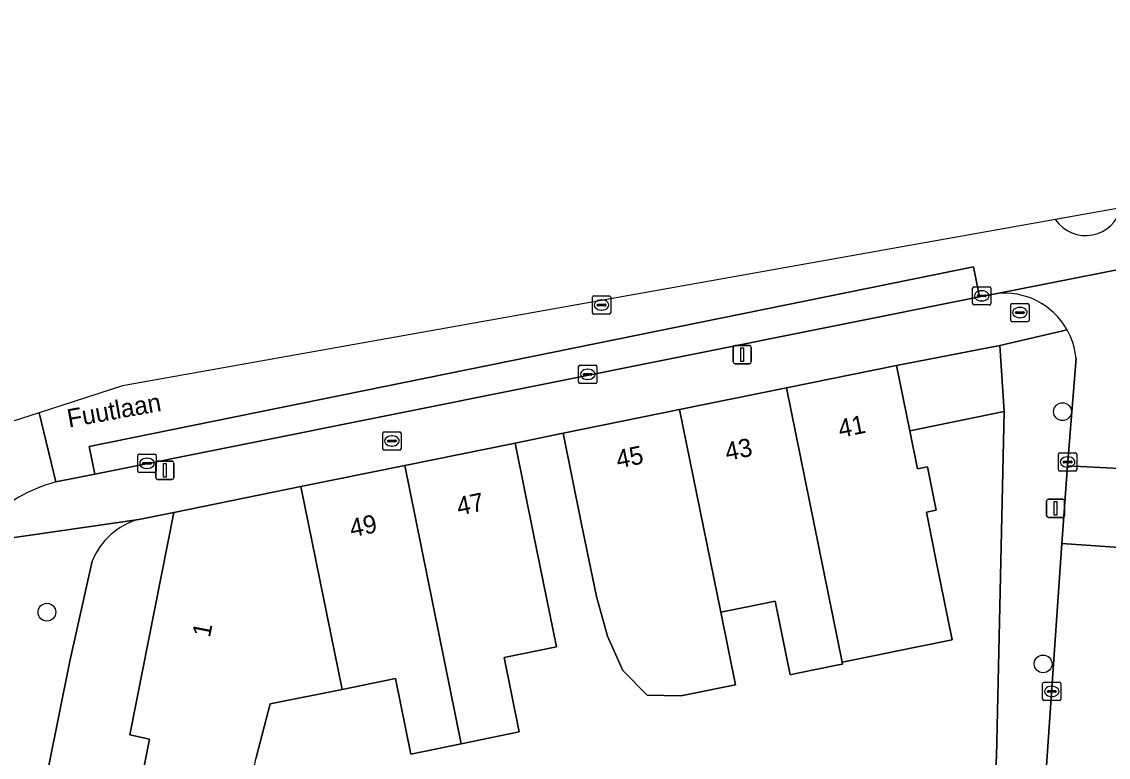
# Model space of a CAD drawing. Extents: x 161772 to 163126, y 383092 to 383917.
# Drawn here: x 162268.2 to 162327.9, y 383778.3 to 383818.6 of the extents above; entities that cross this region are included whole.
import ezdxf

# ---------------------------------------------------------------- set-up
doc = ezdxf.new("R2010")
doc.units = 0
for name, color, linetype in [('IMGEO_Boom', 7, 'Continuous'), ('IMGEO_Brandkraan', 7, 'Continuous'), ('IMGEO_Erf', 7, 'Continuous'), ('IMGEO_Kolk', 7, 'Continuous'), ('IMGEO_Lichtmast', 7, 'Continuous'), ('IMGEO_Openbare_ruimte_label', 7, 'Continuous'), ('IMGEO_Pand', 7, 'Continuous'), ('IMGEO_Pand_nummerreeks', 7, 'Continuous'), ('IMGEO_Parkeervlak_open', 7, 'Continuous'), ('IMGEO_Rijbaan_lokaal_open', 7, 'Continuous'), ('IMGEO_Rioolput', 7, 'Continuous'), ('IMGEO_Voetpad_open', 7, 'Continuous')]:
    doc.layers.add(name, color=color, linetype=linetype)

msp = doc.modelspace()

# ---------------------------------------------------------------- linework, layer by layer
at = {"layer": 'IMGEO_Boom'}
for centre in [(162325.344, 383797.219), (162269.629, 383786.219), (162324.279, 383783.385)]:
    msp.add_circle(centre, 0.489, dxfattribs=at)
at = {"layer": 'IMGEO_Brandkraan'}
for p, q in [((162322.507, 383802.226), (162322.507, 383803.078)), ((162322.582, 383803.152), (162323.434, 383803.152)), ((162323.508, 383803.078), (162323.508, 383802.226)), ((162322.766, 383802.646), (162322.766, 383802.658)), ((162323.204, 383802.609), (162322.806, 383802.609)), ((162322.809, 383802.695), (162323.207, 383802.695)), ((162322.995, 383802.932), (162323.02, 383802.932)), ((162323.25, 383802.658), (162323.25, 383802.646)), ((162323.434, 383802.152), (162322.582, 383802.152)), ((162323.018, 383802.372), (162322.993, 383802.372)), ((162288.055, 383795.184), (162288.055, 383796.036)), ((162288.13, 383796.11), (162288.982, 383796.11)), ((162288.543, 383795.89), (162288.568, 383795.89)), ((162289.056, 383796.036), (162289.056, 383795.184)), ((162288.314, 383795.604), (162288.314, 383795.616)), ((162288.752, 383795.567), (162288.354, 383795.567)), ((162288.357, 383795.653), (162288.755, 383795.653)), ((162288.566, 383795.33), (162288.541, 383795.33)), ((162288.798, 383795.616), (162288.798, 383795.604)), ((162288.982, 383795.11), (162288.13, 383795.11))]:
    msp.add_line(p, q, dxfattribs=at)
for points in [[(162322.507, 383802.226), (162322.507, 383803.078)], [(162322.582, 383803.152), (162323.434, 383803.152)], [(162323.508, 383803.078), (162323.508, 383802.226)], [(162323.434, 383802.152), (162322.582, 383802.152)], [(162288.055, 383795.184), (162288.055, 383796.036)], [(162288.13, 383796.11), (162288.982, 383796.11)], [(162289.056, 383796.036), (162289.056, 383795.184)], [(162288.982, 383795.11), (162288.13, 383795.11)]]:
    msp.add_lwpolyline(points, dxfattribs=at)
for centre, radius, start, end in [((162322.584, 383803.076), 0.0765, 91.55205, 178.44795), ((162322.584, 383803.076), 0.0765, 91.55205, 178.44795), ((162323.432, 383803.076), 0.0765, 1.55205, 88.44795), ((162323.432, 383803.076), 0.0765, 1.55205, 88.44795), ((162322.806, 383802.655), 0.0403, 85.87752, 175.75265), ((162322.803, 383802.645), 0.0366, 178.93798, 274.71019), ((162323.207, 383802.652), 0.043, 264.86636, 352.45326), ((162323.211, 383802.657), 0.0386, 1.73085, 96.63898), ((162322.584, 383802.228), 0.0765, 181.55205, 268.44795), ((162322.584, 383802.228), 0.0765, 181.55205, 268.44795), ((162323.432, 383802.228), 0.0765, 271.55205, 358.44795), ((162323.432, 383802.228), 0.0765, 271.55205, 358.44795), ((162288.132, 383796.034), 0.0765, 91.55205, 178.44795), ((162288.132, 383796.034), 0.0765, 91.55205, 178.44795), ((162288.98, 383796.034), 0.0765, 1.55205, 88.44795), ((162288.98, 383796.034), 0.0765, 1.55205, 88.44795), ((162288.354, 383795.613), 0.0403, 85.87752, 175.75265), ((162288.351, 383795.603), 0.0366, 178.93798, 274.71019), ((162288.755, 383795.61), 0.043, 264.86636, 352.45326), ((162288.759, 383795.615), 0.0386, 1.73085, 96.63898), ((162288.132, 383795.186), 0.0765, 181.55205, 268.44795), ((162288.132, 383795.186), 0.0765, 181.55205, 268.44795), ((162288.98, 383795.186), 0.0765, 271.55205, 358.44795), ((162288.98, 383795.186), 0.0765, 271.55205, 358.44795)]:
    msp.add_arc(centre, radius, start, end, dxfattribs=at)
for centre, major_axis, ratio, start_param, end_param in [((162322.994, 383802.652), (-0.387, 0.002), 0.722429, 4.712389, 7.853982), ((162323.019, 383802.652), (-0.39, 0.002), 0.717154, 1.570796, 4.712389), ((162288.542, 383795.61), (-0.387, 0.002), 0.722429, 4.712389, 7.853982), ((162288.567, 383795.61), (-0.39, 0.002), 0.717154, 1.570796, 4.712389)]:
    msp.add_ellipse(centre, major_axis=major_axis, ratio=ratio, start_param=start_param, end_param=end_param, dxfattribs=at)
at = {"layer": 'IMGEO_Erf'}
for points in [[(162319.862, 383750), (162321.727, 383778.3), (162322.139, 383797.223), (162316.967, 383796.173), (162317.392, 383794.081), (162317.931, 383794.19), (162318.413, 383791.815), (162317.874, 383791.705), (162318.457, 383788.836), (162319.295, 383784.711), (162316.12, 383784.066), (162315.248, 383783.889), (162313.255, 383783.484), (162313.276, 383783.377), (162313.058, 383783.333), (162310.891, 383782.893), (162310.398, 383782.793), (162309.58, 383786.821), (162308.063, 383786.513), (162306.602, 383786.217), (162307.41, 383782.245), (162304.407, 383781.634), (162302.554, 383781.68), (162301.226, 383783.033), (162300.375, 383784.913), (162299.786, 383787.082), (162298.945, 383791.139), (162297.95, 383796.038), (162295.313, 383795.494), (162296.309, 383790.595), (162297.584, 383784.328), (162294.712, 383783.744), (162295.544, 383779.654), (162292.357, 383779.006), (162289.591, 383778.444), (162288.749, 383782.585), (162285.824, 383781.991), (162281.88, 383781.189), (162281.098, 383778.183)], [(162272.117, 383789.029), (162270.877, 383783.542), (162269.728, 383777.815), (162274.763, 383776.75), (162275.261, 383779.268), (162274.173, 383779.503), (162276.595, 383791.688)], [(162276.595, 383791.688), (162274.674, 383791.312)]]:
    msp.add_lwpolyline(points, dxfattribs=at)
msp.add_arc((162275.675, 383787.617), 3.828, 105.16115, 158.35856, dxfattribs=at)
at = {"layer": 'IMGEO_Kolk'}
for p, q in [((162320.412, 383803.142), (162320.412, 383803.994)), ((162320.487, 383804.068), (162321.339, 383804.068)), ((162320.714, 383803.611), (162321.112, 383803.611)), ((162320.9, 383803.848), (162320.925, 383803.848)), ((162321.413, 383803.994), (162321.413, 383803.142)), ((162321.339, 383803.068), (162320.487, 383803.068)), ((162320.671, 383803.562), (162320.671, 383803.574)), ((162321.109, 383803.525), (162320.711, 383803.525)), ((162320.923, 383803.288), (162320.898, 383803.288)), ((162321.155, 383803.574), (162321.155, 383803.562)), ((162298.798, 383798.839), (162298.798, 383799.691)), ((162298.873, 383799.765), (162299.725, 383799.765)), ((162299.286, 383799.545), (162299.311, 383799.545)), ((162299.799, 383799.691), (162299.799, 383798.839)), ((162299.057, 383799.259), (162299.057, 383799.271)), ((162299.495, 383799.222), (162299.097, 383799.222)), ((162299.1, 383799.308), (162299.498, 383799.308)), ((162299.309, 383798.985), (162299.284, 383798.985)), ((162299.541, 383799.271), (162299.541, 383799.259)), ((162299.725, 383798.765), (162298.873, 383798.765)), ((162274.619, 383793.959), (162274.619, 383794.811)), ((162274.694, 383794.885), (162275.546, 383794.885)), ((162275.107, 383794.665), (162275.132, 383794.665)), ((162275.62, 383794.811), (162275.62, 383793.959)), ((162325.123, 383794.032), (162325.123, 383794.884)), ((162325.198, 383794.958), (162326.05, 383794.958)), ((162325.611, 383794.738), (162325.636, 383794.738)), ((162326.124, 383794.884), (162326.124, 383794.032)), ((162274.878, 383794.379), (162274.878, 383794.391)), ((162275.316, 383794.342), (162274.918, 383794.342)), ((162274.921, 383794.428), (162275.319, 383794.428)), ((162275.13, 383794.105), (162275.105, 383794.105)), ((162275.362, 383794.391), (162275.362, 383794.379)), ((162325.382, 383794.452), (162325.382, 383794.464)), ((162325.82, 383794.415), (162325.422, 383794.415)), ((162325.425, 383794.501), (162325.823, 383794.501)), ((162325.634, 383794.178), (162325.609, 383794.178)), ((162325.866, 383794.464), (162325.866, 383794.452)), ((162275.546, 383793.885), (162274.694, 383793.885)), ((162326.05, 383793.958), (162325.198, 383793.958)), ((162324.253, 383781.452), (162324.253, 383782.304)), ((162324.328, 383782.378), (162325.18, 383782.378)), ((162324.741, 383782.158), (162324.766, 383782.158)), ((162325.254, 383782.304), (162325.254, 383781.452)), ((162324.512, 383781.872), (162324.512, 383781.884)), ((162324.95, 383781.835), (162324.552, 383781.835)), ((162324.555, 383781.921), (162324.953, 383781.921)), ((162324.764, 383781.598), (162324.739, 383781.598)), ((162324.996, 383781.884), (162324.996, 383781.872)), ((162325.18, 383781.378), (162324.328, 383781.378))]:
    msp.add_line(p, q, dxfattribs=at)
for points in [[(162320.412, 383803.142), (162320.412, 383803.994)], [(162320.487, 383804.068), (162321.339, 383804.068)], [(162321.413, 383803.994), (162321.413, 383803.142)], [(162321.339, 383803.068), (162320.487, 383803.068)], [(162298.798, 383798.839), (162298.798, 383799.691)], [(162298.873, 383799.765), (162299.725, 383799.765)], [(162299.799, 383799.691), (162299.799, 383798.839)], [(162299.725, 383798.765), (162298.873, 383798.765)], [(162274.619, 383793.959), (162274.619, 383794.811)], [(162274.694, 383794.885), (162275.546, 383794.885)], [(162275.62, 383794.811), (162275.62, 383793.959)], [(162325.123, 383794.032), (162325.123, 383794.884)], [(162325.198, 383794.958), (162326.05, 383794.958)], [(162326.124, 383794.884), (162326.124, 383794.032)], [(162275.546, 383793.885), (162274.694, 383793.885)], [(162326.05, 383793.958), (162325.198, 383793.958)], [(162324.253, 383781.452), (162324.253, 383782.304)], [(162324.328, 383782.378), (162325.18, 383782.378)], [(162325.254, 383782.304), (162325.254, 383781.452)], [(162325.18, 383781.378), (162324.328, 383781.378)]]:
    msp.add_lwpolyline(points, dxfattribs=at)
for centre, radius, start, end in [((162320.489, 383803.992), 0.0765, 91.55205, 178.44795), ((162320.489, 383803.992), 0.0765, 91.55205, 178.44795), ((162320.711, 383803.571), 0.0403, 85.87752, 175.75265), ((162321.116, 383803.573), 0.0386, 1.73085, 96.63898), ((162321.337, 383803.992), 0.0765, 1.55205, 88.44795), ((162321.337, 383803.992), 0.0765, 1.55205, 88.44795), ((162320.489, 383803.144), 0.0765, 181.55205, 268.44795), ((162320.489, 383803.144), 0.0765, 181.55205, 268.44795), ((162320.708, 383803.561), 0.0366, 178.93798, 274.71019), ((162321.112, 383803.568), 0.043, 264.86636, 352.45326), ((162321.337, 383803.144), 0.0765, 271.55205, 358.44795), ((162321.337, 383803.144), 0.0765, 271.55205, 358.44795), ((162298.875, 383799.689), 0.0765, 91.55205, 178.44795), ((162298.875, 383799.689), 0.0765, 91.55205, 178.44795), ((162299.723, 383799.689), 0.0765, 1.55205, 88.44795), ((162299.723, 383799.689), 0.0765, 1.55205, 88.44795), ((162298.875, 383798.841), 0.0765, 181.55205, 268.44795), ((162298.875, 383798.841), 0.0765, 181.55205, 268.44795), ((162299.097, 383799.268), 0.0403, 85.87752, 175.75265), ((162299.094, 383799.258), 0.0366, 178.93798, 274.71019), ((162299.498, 383799.265), 0.043, 264.86636, 352.45326), ((162299.502, 383799.27), 0.0386, 1.73085, 96.63898), ((162299.723, 383798.841), 0.0765, 271.55205, 358.44795), ((162299.723, 383798.841), 0.0765, 271.55205, 358.44795), ((162274.696, 383794.809), 0.0765, 91.55205, 178.44795), ((162274.696, 383794.809), 0.0765, 91.55205, 178.44795), ((162275.544, 383794.809), 0.0765, 1.55205, 88.44795), ((162275.544, 383794.809), 0.0765, 1.55205, 88.44795), ((162325.2, 383794.882), 0.0765, 91.55205, 178.44795), ((162325.2, 383794.882), 0.0765, 91.55205, 178.44795), ((162326.048, 383794.882), 0.0765, 1.55205, 88.44795), ((162326.048, 383794.882), 0.0765, 1.55205, 88.44795), ((162274.918, 383794.388), 0.0403, 85.87752, 175.75265), ((162274.915, 383794.378), 0.0366, 178.93798, 274.71019), ((162275.319, 383794.385), 0.043, 264.86636, 352.45326), ((162275.323, 383794.39), 0.0386, 1.73085, 96.63898), ((162325.422, 383794.461), 0.0403, 85.87752, 175.75265), ((162325.419, 383794.451), 0.0366, 178.93798, 274.71019), ((162325.823, 383794.458), 0.043, 264.86636, 352.45326), ((162325.827, 383794.463), 0.0386, 1.73085, 96.63898), ((162274.696, 383793.961), 0.0765, 181.55205, 268.44795), ((162274.696, 383793.961), 0.0765, 181.55205, 268.44795), ((162275.544, 383793.961), 0.0765, 271.55205, 358.44795), ((162275.544, 383793.961), 0.0765, 271.55205, 358.44795), ((162325.2, 383794.034), 0.0765, 181.55205, 268.44795), ((162325.2, 383794.034), 0.0765, 181.55205, 268.44795), ((162326.048, 383794.034), 0.0765, 271.55205, 358.44795), ((162326.048, 383794.034), 0.0765, 271.55205, 358.44795), ((162324.33, 383782.302), 0.0765, 91.55205, 178.44795), ((162324.33, 383782.302), 0.0765, 91.55205, 178.44795), ((162325.178, 383782.302), 0.0765, 1.55205, 88.44795), ((162325.178, 383782.302), 0.0765, 1.55205, 88.44795), ((162324.552, 383781.881), 0.0403, 85.87752, 175.75265), ((162324.549, 383781.871), 0.0366, 178.93798, 274.71019), ((162324.953, 383781.878), 0.043, 264.86636, 352.45326), ((162324.957, 383781.883), 0.0386, 1.73085, 96.63898), ((162324.33, 383781.454), 0.0765, 181.55205, 268.44795), ((162324.33, 383781.454), 0.0765, 181.55205, 268.44795), ((162325.178, 383781.454), 0.0765, 271.55205, 358.44795), ((162325.178, 383781.454), 0.0765, 271.55205, 358.44795)]:
    msp.add_arc(centre, radius, start, end, dxfattribs=at)
for centre, major_axis, ratio, start_param, end_param in [((162320.899, 383803.568), (-0.387, 0.002), 0.722429, 4.712389, 7.853982), ((162320.924, 383803.568), (-0.39, 0.002), 0.717154, 1.570796, 4.712389), ((162299.285, 383799.265), (-0.387, 0.002), 0.722429, 4.712389, 7.853982), ((162299.31, 383799.265), (-0.39, 0.002), 0.717154, 1.570796, 4.712389), ((162275.106, 383794.385), (-0.387, 0.002), 0.722429, 4.712389, 7.853982), ((162275.131, 383794.385), (-0.39, 0.002), 0.717154, 1.570796, 4.712389), ((162325.61, 383794.458), (-0.387, 0.002), 0.722429, 4.712389, 7.853982), ((162325.635, 383794.458), (-0.39, 0.002), 0.717154, 1.570796, 4.712389), ((162324.74, 383781.878), (-0.387, 0.002), 0.722429, 4.712389, 7.853982), ((162324.765, 383781.878), (-0.39, 0.002), 0.717154, 1.570796, 4.712389)]:
    msp.add_ellipse(centre, major_axis=major_axis, ratio=ratio, start_param=start_param, end_param=end_param, dxfattribs=at)
at = {"layer": 'IMGEO_Lichtmast'}
for p, q in [((162307.281, 383799.949), (162307.281, 383800.749)), ((162307.281, 383800.749), (162307.281, 383799.949)), ((162307.381, 383800.849), (162308.171, 383800.849)), ((162308.171, 383800.849), (162307.381, 383800.849)), ((162308.271, 383800.749), (162308.271, 383799.949)), ((162308.271, 383799.949), (162308.271, 383800.749)), ((162308.171, 383799.849), (162307.381, 383799.849)), ((162307.381, 383799.849), (162308.171, 383799.849)), ((162275.603, 383793.596), (162275.603, 383794.396)), ((162275.603, 383794.396), (162275.603, 383793.596)), ((162275.703, 383794.496), (162276.493, 383794.496)), ((162276.493, 383794.496), (162275.703, 383794.496)), ((162276.593, 383794.396), (162276.593, 383793.596)), ((162276.593, 383793.596), (162276.593, 383794.396)), ((162276.493, 383793.496), (162275.703, 383793.496)), ((162275.703, 383793.496), (162276.493, 383793.496)), ((162324.468, 383791.515), (162324.468, 383792.315)), ((162324.468, 383792.315), (162324.468, 383791.515)), ((162324.568, 383792.415), (162325.358, 383792.415)), ((162325.358, 383792.415), (162324.568, 383792.415)), ((162325.458, 383792.315), (162325.458, 383791.515)), ((162325.458, 383791.515), (162325.458, 383792.315)), ((162325.358, 383791.415), (162324.568, 383791.415)), ((162324.568, 383791.415), (162325.358, 383791.415))]:
    msp.add_line(p, q, dxfattribs=at)
for points in [[(162307.701, 383800.724), (162307.851, 383800.724), (162307.851, 383799.974), (162307.701, 383799.974), (162307.701, 383800.724)], [(162276.023, 383794.371), (162276.173, 383794.371), (162276.173, 383793.621), (162276.023, 383793.621), (162276.023, 383794.371)], [(162324.888, 383792.29), (162325.038, 383792.29), (162325.038, 383791.54), (162324.888, 383791.54), (162324.888, 383792.29)]]:
    msp.add_lwpolyline(points, dxfattribs=at)
for centre, start, end in [((162307.381, 383800.749), 90, 180), ((162307.381, 383800.749), 90, 180), ((162308.171, 383800.749), 0, 90), ((162308.171, 383800.749), 360, 90), ((162307.381, 383799.949), 180, 270), ((162307.381, 383799.949), 180, 270), ((162308.171, 383799.949), 270, 0), ((162308.171, 383799.949), 270, 0), ((162275.703, 383794.396), 90, 180), ((162275.703, 383794.396), 90, 180), ((162276.493, 383794.396), 0, 90), ((162276.493, 383794.396), 360, 90), ((162275.703, 383793.596), 180, 270), ((162275.703, 383793.596), 180, 270), ((162276.493, 383793.596), 270, 0), ((162276.493, 383793.596), 270, 0), ((162324.568, 383792.315), 90, 180), ((162324.568, 383792.315), 90, 180), ((162325.358, 383792.315), 0, 90), ((162325.358, 383792.315), 360, 90), ((162324.568, 383791.515), 180, 270), ((162324.568, 383791.515), 180, 270), ((162325.358, 383791.515), 270, 0), ((162325.358, 383791.515), 270, 0)]:
    msp.add_arc(centre, 0.1, start, end, dxfattribs=at)
at = {"layer": 'IMGEO_Pand'}
for points in [[(162321.904, 383800.852), (162316.24, 383799.753), (162316.967, 383796.173), (162322.139, 383797.223)], [(162318.413, 383791.815), (162317.931, 383794.19), (162317.392, 383794.081), (162316.967, 383796.173), (162316.24, 383799.753), (162310.196, 383798.525), (162313.255, 383783.484), (162315.248, 383783.889), (162316.12, 383784.066), (162319.295, 383784.711), (162318.457, 383788.836), (162317.874, 383791.705)], [(162310.196, 383798.525), (162304.341, 383797.336), (162306.602, 383786.217), (162308.063, 383786.513), (162309.58, 383786.821), (162310.398, 383782.793), (162310.891, 383782.893), (162313.058, 383783.333), (162313.276, 383783.377), (162313.255, 383783.484)], [(162304.341, 383797.336), (162297.95, 383796.038), (162298.945, 383791.139), (162299.786, 383787.082), (162300.375, 383784.913), (162301.226, 383783.033), (162302.554, 383781.68), (162304.407, 383781.634), (162307.41, 383782.245), (162306.602, 383786.217)], [(162289.259, 383794.263), (162292.357, 383779.006), (162295.544, 383779.654), (162294.712, 383783.744), (162297.584, 383784.328), (162296.309, 383790.595), (162295.313, 383795.494)], [(162283.567, 383793.106), (162285.824, 383781.991), (162288.749, 383782.585), (162289.591, 383778.444), (162292.357, 383779.006), (162289.259, 383794.263)], [(162283.567, 383793.106), (162276.595, 383791.688), (162274.173, 383779.503), (162275.261, 383779.268), (162274.763, 383776.75), (162276.722, 383776.385), (162280.593, 383775.63), (162281.098, 383778.183), (162281.88, 383781.189), (162285.824, 383781.991)]]:
    msp.add_lwpolyline(points, close=True, dxfattribs=at)
at = {"layer": 'IMGEO_Parkeervlak_open'}
msp.add_lwpolyline([(162320.785, 383803.509), (162320.467, 383805.155), (162271.954, 383795.306), (162272.251, 383793.788)], close=True, dxfattribs=at)
at = {"layer": 'IMGEO_Rijbaan_lokaal_open'}
for points in [[(162324.958, 383807.747), (162273.78, 383798.628), (162269.209, 383797.162), (162270.117, 383793.362), (162272.251, 383793.788), (162271.954, 383795.306), (162320.467, 383805.155), (162320.785, 383803.509), (162321.677, 383803.688), (162331.68, 383805.652), (162334.52, 383806.219), (162336.626, 383806.639), (162336.258, 383808.477), (162356.207, 383812.475), (162356.578, 383810.623), (162357.425, 383810.792), (162363.977, 383812.1), (162364.516, 383812.208), (162364.144, 383814.066), (162379.699, 383817.183), (162380.073, 383815.315), (162380.997, 383815.499), (162380.397, 383818.601)], [(162328.551, 383808.387), (162324.958, 383807.747)], [(162334.52, 383806.219), (162331.68, 383805.652), (162321.677, 383803.688)], [(162326.088, 383800.147), (162325.61, 383794.248), (162330.618, 383793.983), (162331.32, 383802.125)], [(162270.117, 383793.362), (162269.209, 383797.162), (162254.657, 383792.497)]]:
    msp.add_lwpolyline(points, dxfattribs=at)
for points in [[(162325.316, 383789.988), (162330.319, 383789.642), (162330.326, 383789.743), (162330.618, 383793.983), (162325.61, 383794.248)], [(162327.904, 383754.6), (162328.166, 383758.408), (162330.319, 383789.642), (162325.316, 383789.988), (162322.549, 383750), (162322.2, 383744.798), (162327.215, 383744.461), (162327.587, 383750)]]:
    msp.add_lwpolyline(points, close=True, dxfattribs=at)
for centre, radius, start, end in [((162326.61, 383808.877), 2.002, 281.14496, 345.83134), ((162326.61, 383808.877), 2.002, 281.14496, 345.83134), ((162326.61, 383808.877), 2.002, 214.37449, 281.15006), ((162326.61, 383808.877), 2.002, 214.37449, 281.15006), ((162322.161, 383799.773), 3.945, 29.47794, 97.04153), ((162322.156, 383799.771), 3.95, 5.46135, 29.46725), ((162272.362, 383785.057), 8.603, 105.12827, 134.48212)]:
    msp.add_arc(centre, radius, start, end, dxfattribs=at)
at = {"layer": 'IMGEO_Rioolput'}
for p, q in [((162299.557, 383802.638), (162299.557, 383803.49)), ((162299.632, 383803.564), (162300.484, 383803.564)), ((162299.816, 383803.058), (162299.816, 383803.07)), ((162300.254, 383803.021), (162299.856, 383803.021)), ((162299.859, 383803.107), (162300.257, 383803.107)), ((162300.045, 383803.344), (162300.07, 383803.344)), ((162300.3, 383803.07), (162300.3, 383803.058)), ((162300.558, 383803.49), (162300.558, 383802.638)), ((162300.484, 383802.564), (162299.632, 383802.564)), ((162300.068, 383802.784), (162300.043, 383802.784))]:
    msp.add_line(p, q, dxfattribs=at)
for points in [[(162299.557, 383802.638), (162299.557, 383803.49)], [(162299.632, 383803.564), (162300.484, 383803.564)], [(162300.558, 383803.49), (162300.558, 383802.638)], [(162300.484, 383802.564), (162299.632, 383802.564)]]:
    msp.add_lwpolyline(points, dxfattribs=at)
for centre, radius, start, end in [((162299.634, 383803.488), 0.0765, 91.55205, 178.44795), ((162299.634, 383803.488), 0.0765, 91.55205, 178.44795), ((162299.856, 383803.067), 0.0403, 85.87752, 175.75265), ((162299.853, 383803.057), 0.0366, 178.93798, 274.71019), ((162300.257, 383803.064), 0.043, 264.86636, 352.45326), ((162300.261, 383803.069), 0.0386, 1.73085, 96.63898), ((162300.482, 383803.488), 0.0765, 1.55205, 88.44795), ((162300.482, 383803.488), 0.0765, 1.55205, 88.44795), ((162299.634, 383802.64), 0.0765, 181.55205, 268.44795), ((162299.634, 383802.64), 0.0765, 181.55205, 268.44795), ((162300.482, 383802.64), 0.0765, 271.55205, 358.44795), ((162300.482, 383802.64), 0.0765, 271.55205, 358.44795)]:
    msp.add_arc(centre, radius, start, end, dxfattribs=at)
for centre, major_axis, ratio, start_param, end_param in [((162300.044, 383803.064), (-0.387, 0.002), 0.722429, 4.712389, 7.853982), ((162300.069, 383803.064), (-0.39, 0.002), 0.717154, 1.570796, 4.712389)]:
    msp.add_ellipse(centre, major_axis=major_axis, ratio=ratio, start_param=start_param, end_param=end_param, dxfattribs=at)
at = {"layer": 'IMGEO_Voetpad_open'}
for points in [[(162321.677, 383803.688), (162320.785, 383803.509), (162272.251, 383793.788), (162270.117, 383793.362)], [(162304.341, 383797.336), (162310.196, 383798.525), (162316.24, 383799.753), (162321.904, 383800.852), (162325.595, 383801.714)], [(162325.595, 383801.714), (162321.904, 383800.852), (162322.139, 383797.223), (162321.727, 383778.3), (162319.862, 383750), (162317.249, 383713.725), (162313.196, 383652.957), (162312.79, 383644.774), (162310.606, 383642.128), (162314.799, 383642.8)], [(162321.062, 383727.852), (162320.547, 383727.883), (162320.758, 383731.158), (162321.282, 383731.126), (162322.016, 383742.063), (162322.2, 383744.798), (162322.549, 383750), (162325.316, 383789.988), (162325.61, 383794.248), (162326.088, 383800.147)], [(162265.676, 383790.007), (162274.674, 383791.312), (162276.595, 383791.688), (162283.567, 383793.106), (162289.259, 383794.263), (162295.313, 383795.494), (162297.95, 383796.038), (162304.341, 383797.336)], [(162274.674, 383791.312), (162265.676, 383790.007)], [(162255.603, 383707.378), (162255.783, 383708.274), (162264.15, 383750), (162269.552, 383776.935), (162269.728, 383777.815), (162270.877, 383783.542), (162272.117, 383789.029)]]:
    msp.add_lwpolyline(points, dxfattribs=at)
for centre, radius, start, end in [((162322.161, 383799.773), 3.945, 29.47794, 97.04153), ((162322.156, 383799.771), 3.95, 5.46135, 29.46725), ((162272.362, 383785.057), 8.603, 105.12827, 134.48212), ((162275.675, 383787.617), 3.828, 105.16115, 158.35856)]:
    msp.add_arc(centre, radius, start, end, dxfattribs=at)

# ---------------------------------------------------------------- texts
at = {"layer": 'IMGEO_Openbare_ruimte_label'}
msp.add_text('Fuutlaan', height=1, rotation=10.19721, dxfattribs=at).set_placement((162270.835, 383796.345))
at = {"layer": 'IMGEO_Pand_nummerreeks'}
for s, rotation, p in [('41', 11.48207, (162313.146, 383795.777)), ('45', 11.48207, (162300.961, 383794.098)), ('43', 11.48207, (162306.938, 383794.517)), ('47', 11.49348, (162292.22, 383791.518)), ('49', 11.49348, (162286.347, 383790.324)), ('1', 78.75878, (162278.569, 383784.798))]:
    msp.add_text(s, height=1, rotation=rotation, dxfattribs=at).set_placement(p)

doc.saveas('drawing.dxf')
